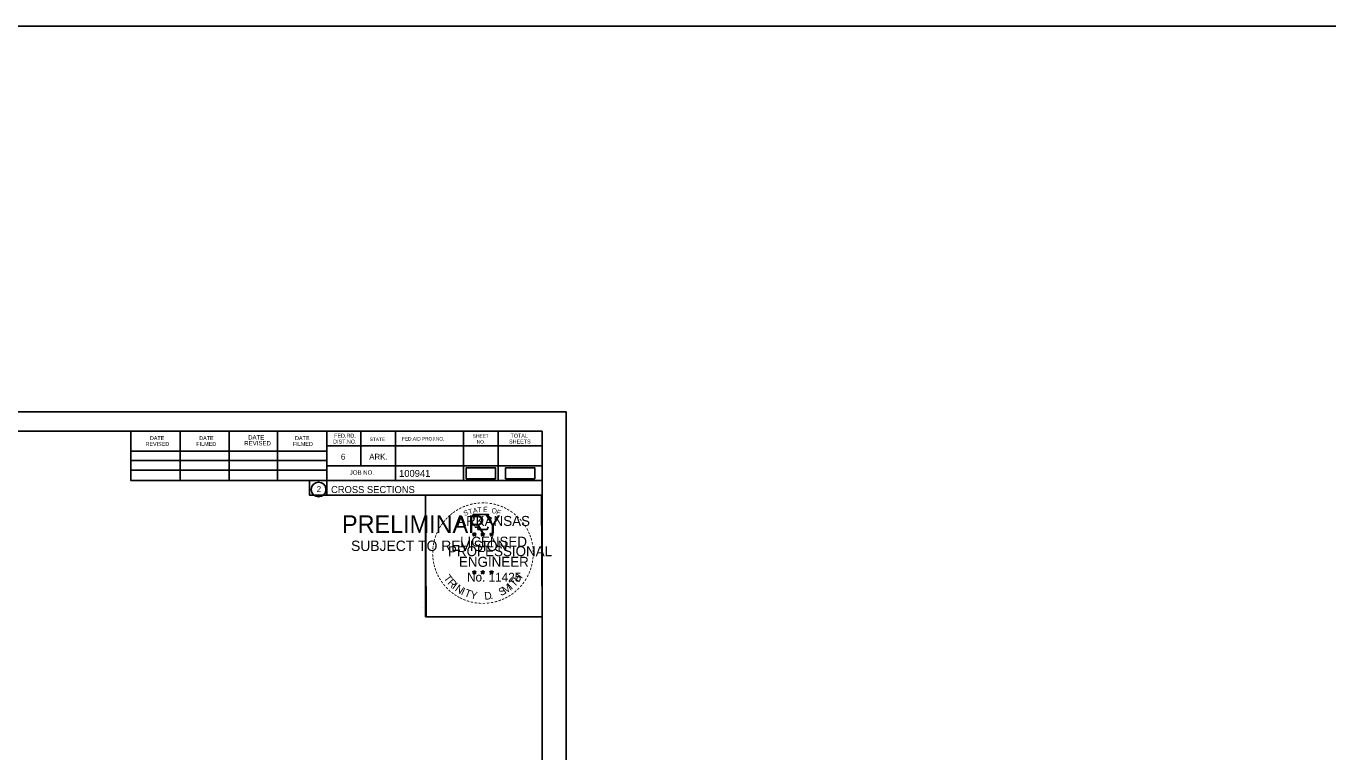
# Model space of a CAD drawing. Extents: x 1370538 to 1372872, y 376220 to 381127.
# Drawn here: x 1372096.9 to 1372357.3, y 380830.3 to 380975.6 of the extents above; entities that cross this region are included whole.
import ezdxf

# ---------------------------------------------------------------- set-up
doc = ezdxf.new("R2010")
doc.units = 0
for name, color, linetype in [('Default', 7, 'Continuous'), ('R_Border Notes', 7, 'Continuous'), ('R_No Plot', 7, 'Continuous'), ('T_Indications', 7, 'Continuous'), ('T_Notes', 7, 'Continuous')]:
    doc.layers.add(name, color=color, linetype=linetype)

msp = doc.modelspace()

# ---------------------------------------------------------------- linework, layer by layer
at = {"layer": 'Default'}
for points in [[(1372184.96, 380885), (1372190.79, 380885), (1372190.79, 380887.19), (1372184.96, 380887.19)], [(1372192.83, 380885), (1372198.66, 380885), (1372198.66, 380887.19), (1372192.83, 380887.19)]]:
    msp.add_lwpolyline(points, close=True, dxfattribs=at)
at = {"layer": 'R_Border Notes'}
for p, q in [((1371883.97, 380894.5), (1372200.15, 380894.5)), ((1372117.89, 380884.62), (1372117.89, 380894.5)), ((1372127.75, 380884.62), (1372127.75, 380894.3)), ((1372137.51, 380884.62), (1372137.51, 380894.3)), ((1372147.19, 380884.62), (1372147.19, 380894.3)), ((1372157.05, 380894.5), (1372157.05, 380881.7)), ((1372163.89, 380894.5), (1372163.89, 380887.56)), ((1372170.83, 380894.5), (1372170.83, 380884.62)), ((1372184.41, 380894.5), (1372184.41, 380884.62)), ((1372191.35, 380894.5), (1372191.35, 380884.62)), ((1372200.15, 380689.04), (1372200.15, 380894.5)), ((1372117.89, 380890.48), (1372157.05, 380890.48)), ((1372200.15, 380891.56), (1372157.05, 380891.56)), ((1372200.15, 380891.58), (1372200.15, 380891.58)), ((1372117.89, 380888.62), (1372157.05, 380888.62)), ((1372117.89, 380884.62), (1372117.89, 380886.68)), ((1372117.89, 380886.68), (1372157.05, 380886.68)), ((1372200.15, 380887.56), (1372157.05, 380887.56)), ((1372160.01, 380887.56), (1372200.15, 380887.56)), ((1372200.15, 380884.62), (1372117.89, 380884.62)), ((1372157.05, 380881.7), (1372200.15, 380881.7))]:
    msp.add_line(p, q, dxfattribs=at)
msp.add_circle((1372155.43, 380882.84), 1.47, dxfattribs=at)
at = {"layer": 'R_No Plot'}
for p, q in [((1370538.2, 380975.58), (1372871.58, 380975.58)), ((1371871.57, 380898.4), (1372204.9, 380898.4)), ((1372176.18, 380859.25), (1372176.18, 380859.25))]:
    msp.add_line(p, q, dxfattribs=at)
for points in [[(1371871.56, 380898.4), (1372204.9, 380898.4), (1372204.9, 380685.06), (1371871.56, 380685.06)], [(1372117.89, 380894.5), (1372117.89, 380884.62), (1372153.62, 380884.62), (1372153.62, 380881.7), (1372176.82, 380881.7), (1372176.82, 380857.37), (1372200.15, 380857.37), (1372200.15, 380689.04), (1371883.97, 380689.04), (1371883.97, 380894.5)], [(1372176.82, 380881.7), (1372200.03, 380881.7), (1372200.15, 380857.37), (1372176.94, 380857.37)]]:
    msp.add_lwpolyline(points, close=True, dxfattribs=at)
at = {"layer": 'T_Indications'}
for p, q in [((1372186.23, 380873.96), (1372186.58, 380873.85)), ((1372186.23, 380873.96), (1372186.48, 380873.91)), ((1372186.23, 380873.96), (1372186.47, 380873.84)), ((1372186.36, 380873.55), (1372186.58, 380873.85)), ((1372186.36, 380873.55), (1372186.49, 380873.8)), ((1372186.36, 380873.55), (1372186.58, 380873.77)), ((1372186.58, 380874.21), (1372186.54, 380873.96)), ((1372186.58, 380873.85), (1372186.58, 380874.21)), ((1372186.58, 380874.21), (1372186.63, 380873.96)), ((1372186.93, 380873.96), (1372186.58, 380873.85)), ((1372186.79, 380873.55), (1372186.58, 380873.85)), ((1372186.79, 380873.55), (1372186.58, 380873.77)), ((1372186.93, 380873.96), (1372186.64, 380873.91)), ((1372186.79, 380873.55), (1372186.66, 380873.84)), ((1372186.93, 380873.96), (1372186.72, 380873.86)), ((1372187.9, 380873.96), (1372188.25, 380873.85)), ((1372187.9, 380873.96), (1372188.15, 380873.91)), ((1372187.9, 380873.96), (1372188.14, 380873.84)), ((1372188.03, 380873.55), (1372188.25, 380873.85)), ((1372188.03, 380873.55), (1372188.16, 380873.8)), ((1372188.03, 380873.55), (1372188.25, 380873.77)), ((1372188.25, 380874.21), (1372188.21, 380873.96)), ((1372188.25, 380873.85), (1372188.25, 380874.21)), ((1372188.25, 380874.21), (1372188.3, 380873.96)), ((1372188.6, 380873.96), (1372188.25, 380873.85)), ((1372188.46, 380873.55), (1372188.25, 380873.85)), ((1372188.46, 380873.55), (1372188.25, 380873.77)), ((1372188.6, 380873.96), (1372188.31, 380873.91)), ((1372188.46, 380873.55), (1372188.33, 380873.84)), ((1372188.6, 380873.96), (1372188.39, 380873.86)), ((1372189.67, 380873.95), (1372190.01, 380873.84)), ((1372189.67, 380873.95), (1372189.92, 380873.9)), ((1372189.67, 380873.95), (1372189.9, 380873.83)), ((1372189.8, 380873.54), (1372190.01, 380873.84)), ((1372189.8, 380873.54), (1372189.92, 380873.78)), ((1372189.8, 380873.54), (1372190.01, 380873.76)), ((1372190.01, 380874.2), (1372189.97, 380873.95)), ((1372190.01, 380873.84), (1372190.01, 380874.2)), ((1372190.01, 380874.2), (1372190.06, 380873.95)), ((1372190.36, 380873.95), (1372190.01, 380873.84)), ((1372190.23, 380873.54), (1372190.01, 380873.84)), ((1372190.23, 380873.54), (1372190.01, 380873.75)), ((1372190.36, 380873.95), (1372190.08, 380873.9)), ((1372190.23, 380873.54), (1372190.09, 380873.83)), ((1372190.36, 380873.95), (1372190.16, 380873.85)), ((1372186.23, 380866.39), (1372186.58, 380866.28)), ((1372186.23, 380866.39), (1372186.48, 380866.34)), ((1372186.23, 380866.39), (1372186.46, 380866.26)), ((1372186.36, 380865.98), (1372186.58, 380866.28)), ((1372186.36, 380865.98), (1372186.49, 380866.22)), ((1372186.36, 380865.98), (1372186.57, 380866.2)), ((1372186.58, 380866.64), (1372186.54, 380866.39)), ((1372186.79, 380865.98), (1372186.57, 380866.19)), ((1372186.58, 380866.28), (1372186.58, 380866.64)), ((1372186.58, 380866.64), (1372186.63, 380866.39)), ((1372186.92, 380866.39), (1372186.58, 380866.28)), ((1372186.79, 380865.98), (1372186.58, 380866.28)), ((1372186.92, 380866.39), (1372186.64, 380866.34)), ((1372186.79, 380865.98), (1372186.65, 380866.27)), ((1372186.92, 380866.39), (1372186.72, 380866.28)), ((1372187.9, 380866.39), (1372188.25, 380866.28)), ((1372187.9, 380866.39), (1372188.15, 380866.34)), ((1372187.9, 380866.39), (1372188.13, 380866.26)), ((1372188.03, 380865.98), (1372188.25, 380866.28)), ((1372188.03, 380865.98), (1372188.16, 380866.22)), ((1372188.03, 380865.98), (1372188.24, 380866.2)), ((1372188.25, 380866.64), (1372188.2, 380866.39)), ((1372188.46, 380865.98), (1372188.24, 380866.19)), ((1372188.25, 380866.28), (1372188.25, 380866.64)), ((1372188.25, 380866.64), (1372188.29, 380866.39)), ((1372188.59, 380866.39), (1372188.25, 380866.28)), ((1372188.46, 380865.98), (1372188.25, 380866.28)), ((1372188.59, 380866.39), (1372188.31, 380866.34)), ((1372188.46, 380865.98), (1372188.32, 380866.27)), ((1372188.59, 380866.39), (1372188.39, 380866.28)), ((1372189.66, 380866.38), (1372190.01, 380866.27)), ((1372189.66, 380866.38), (1372189.92, 380866.33)), ((1372189.66, 380866.38), (1372189.9, 380866.25)), ((1372189.8, 380865.97), (1372190.01, 380866.27)), ((1372189.8, 380865.97), (1372189.92, 380866.21)), ((1372189.8, 380865.97), (1372190.01, 380866.19)), ((1372190.01, 380866.63), (1372189.97, 380866.38)), ((1372190.01, 380866.27), (1372190.01, 380866.63)), ((1372190.01, 380866.63), (1372190.06, 380866.38)), ((1372190.36, 380866.38), (1372190.01, 380866.27)), ((1372190.23, 380865.97), (1372190.01, 380866.27)), ((1372190.23, 380865.97), (1372190.01, 380866.18)), ((1372190.36, 380866.38), (1372190.07, 380866.33)), ((1372190.23, 380865.97), (1372190.09, 380866.26)), ((1372190.36, 380866.38), (1372190.16, 380866.27))]:
    msp.add_line(p, q, dxfattribs=at)
for points in [[(1372186.27, 380877.84), (1372186.54, 380877.01)], [(1372189.78, 380876.92), (1372189.93, 380877.2), (1372189.24, 380877.18), (1372189.39, 380877.84), (1372186.27, 380877.84)], [(1372186.76, 380875.41), (1372186.76, 380875.33), (1372187.33, 380875.31), (1372187.27, 380874.84), (1372189.14, 380874.84), (1372189.34, 380875.37)], [(1372186.58, 380874.21), (1372186.79, 380873.55), (1372186.23, 380873.96), (1372186.93, 380873.96), (1372186.36, 380873.55), (1372186.58, 380874.21)], [(1372188.25, 380874.21), (1372188.46, 380873.55), (1372187.9, 380873.96), (1372188.6, 380873.96), (1372188.03, 380873.55), (1372188.25, 380874.21)], [(1372190.01, 380874.2), (1372190.23, 380873.54), (1372189.67, 380873.95), (1372190.36, 380873.95), (1372189.8, 380873.54), (1372190.01, 380874.2)], [(1372186.58, 380866.64), (1372186.79, 380865.98), (1372186.23, 380866.39), (1372186.92, 380866.39), (1372186.36, 380865.98), (1372186.58, 380866.64)], [(1372188.25, 380866.64), (1372188.46, 380865.98), (1372187.9, 380866.39), (1372188.59, 380866.39), (1372188.03, 380865.98), (1372188.25, 380866.64)], [(1372190.01, 380866.63), (1372190.23, 380865.97), (1372189.66, 380866.38), (1372190.36, 380866.38), (1372189.8, 380865.97), (1372190.01, 380866.63)]]:
    msp.add_lwpolyline(points, dxfattribs=at)
for centre, radius in [((1372186.58, 380873.85), 0.172), ((1372186.58, 380873.85), 0.145), ((1372186.58, 380873.85), 0.116), ((1372186.58, 380873.85), 0.0991), ((1372186.58, 380873.85), 0.0747), ((1372186.58, 380873.85), 0.0495), ((1372186.58, 380873.85), 0.0296), ((1372188.25, 380873.85), 0.172), ((1372188.25, 380873.85), 0.145), ((1372188.25, 380873.85), 0.116), ((1372188.25, 380873.85), 0.0991), ((1372188.25, 380873.85), 0.0747), ((1372188.25, 380873.85), 0.0495), ((1372188.25, 380873.85), 0.0296), ((1372190.01, 380873.84), 0.172), ((1372190.01, 380873.84), 0.145), ((1372190.01, 380873.84), 0.116), ((1372190.01, 380873.84), 0.0991), ((1372190.01, 380873.84), 0.0747), ((1372190.01, 380873.84), 0.0495), ((1372190.01, 380873.84), 0.0296), ((1372186.58, 380866.27), 0.172), ((1372186.58, 380866.27), 0.145), ((1372186.58, 380866.27), 0.116), ((1372186.58, 380866.27), 0.0991), ((1372186.58, 380866.27), 0.0747), ((1372186.58, 380866.27), 0.0495), ((1372186.58, 380866.27), 0.0296), ((1372188.24, 380866.27), 0.172), ((1372188.24, 380866.27), 0.145), ((1372188.24, 380866.27), 0.116), ((1372188.24, 380866.27), 0.0991), ((1372188.24, 380866.27), 0.0747), ((1372188.24, 380866.27), 0.0495), ((1372188.24, 380866.27), 0.0296), ((1372190.01, 380866.26), 0.172), ((1372190.01, 380866.26), 0.145), ((1372190.01, 380866.26), 0.116), ((1372190.01, 380866.26), 0.0991), ((1372190.01, 380866.26), 0.0747), ((1372190.01, 380866.26), 0.0495), ((1372190.01, 380866.26), 0.0296)]:
    msp.add_circle(centre, radius, dxfattribs=at)

# ---------------------------------------------------------------- texts
at = {"layer": 'R_Border Notes'}
for s, height, p in [('DATE', 0.782, (1372121.69, 380892.74)), ('DATE', 0.782, (1372131.55, 380892.74)), ('DATE', 0.879, (1372141.33, 380892.84)), ('DATE', 0.782, (1372150.71, 380892.74)), ('FED.RD.', 0.782, (1372158.53, 380893.22)), ('STATE', 0.684, (1372165.65, 380892.54)), ('FED.AID PROJ.NO.', 0.684, (1372172.11, 380892.64)), ('SHEET', 0.684, (1372186.27, 380893.22)), ('TOTAL', 0.782, (1372193.79, 380893.22)), ('REVISED', 0.782, (1372120.81, 380891.56)), ('FILMED', 0.782, (1372130.97, 380891.56)), ('REVISED', 0.879, (1372140.55, 380891.66)), ('FILMED', 0.782, (1372150.31, 380891.56)), ('DIST.NO.', 0.782, (1372158.33, 380892.04)), ('NO.', 0.684, (1372187.05, 380892.04)), ('SHEETS', 0.782, (1372193.51, 380892.04)), ('6', 1.17, (1372159.89, 380888.82)), ('ARK.', 1.172, (1372165.55, 380888.82)), ('JOB NO.', 0.879, (1372161.65, 380885.8)), ('100941', 1.4, (1372171.52, 380885.36)), ('2', 1.17, (1372155.05, 380882.35)), ('CROSS SECTIONS', 1.4, (1372157.91, 380882.13))]:
    msp.add_text(s, height=height, rotation=360, dxfattribs=at).set_placement(p)
at = {"layer": 'T_Indications'}
for s, height, rotation, p in [('-', 1.6, 13.6301, (1372185.77, 380879.21)), ('-', 1.6, 10.2193, (1372186.45, 380879.37)), ('-', 1.6, 5.8968, (1372187.18, 380879.48)), ('-', 1.6, 0.1862, (1372187.95, 380879.55)), ('-', 1.6, 357.743, (1372188.67, 380879.54)), ('-', 1.6, 352.1617, (1372189.42, 380879.48)), ('-', 1.6, 347.2049, (1372190.14, 380879.37)), ('-', 1.6, 342.3362, (1372190.77, 380879.21)), ('-', 1.6, 48.423, (1372181.22, 380876.34)), ('-', 1.6, 42.9622, (1372181.67, 380876.82)), ('-', 1.6, 38.9507, (1372182.1, 380877.24)), ('-', 1.6, 36.2317, (1372182.58, 380877.61)), ('-', 1.6, 34.0636, (1372183.16, 380878.01)), ('ARKANSAS', 2, 360, (1372183.13, 380875.55)), ('-', 1.6, 28.7918, (1372183.75, 380878.38)), ('-', 1.6, 24.3072, (1372184.39, 380878.7)), ('S', 1, 21.594, (1372184.63, 380877.52)), ('-', 1.6, 19.1761, (1372185.02, 380878.96)), ('T', 1, 16.4036, (1372185.54, 380877.85)), ('A', 1, 11.2132, (1372186.37, 380878.1)), ('T', 1, 6.0228, (1372187.22, 380878.26)), ('E', 1, 0.8323, (1372188.32, 380878.37)), ('O', 1, 350.4515, (1372189.93, 380878.16)), ('F', 1, 340.0707, (1372190.88, 380877.94)), ('-', 1.6, 337.8551, (1372191.51, 380878.99)), ('-', 1.6, 334.1211, (1372192.14, 380878.72)), ('-', 1.6, 329.6409, (1372192.72, 380878.43)), ('-', 1.6, 325.8627, (1372193.36, 380878.07)), ('-', 1.6, 320.5297, (1372193.97, 380877.65)), ('-', 1.6, 315.5786, (1372194.57, 380877.16)), ('-', 1.6, 62.8713, (1372179.77, 380874.15)), ('-', 1.6, 58.0706, (1372180.08, 380874.76)), ('-', 1.6, 54.2325, (1372180.41, 380875.29)), ('-', 1.6, 50.6142, (1372180.82, 380875.85)), ('-', 1.6, 309.8797, (1372195.14, 380876.61)), ('-', 1.6, 306.6522, (1372195.66, 380876.01)), ('-', 1.4, 303.6753, (1372196.15, 380875.44)), ('-', 1.6, 299.6684, (1372196.47, 380874.83)), ('-', 1.6, 81.2013, (1372178.96, 380871.48)), ('-', 1.6, 75.461, (1372179.09, 380872.19)), ('-', 1.6, 72.3945, (1372179.29, 380872.91)), ('-', 1.6, 67.7743, (1372179.51, 380873.54)), ('LICENSED', 2, 360, (1372183.72, 380871.4)), ('DWB', 0.01, 360, (1372186.57, 380873.84)), ('DWB', 0.01, 360, (1372188.24, 380873.84)), ('DWB', 0.01, 360, (1372190, 380873.83)), ('-', 1.6, 294.6628, (1372196.79, 380874.22)), ('-', 1.6, 290.5728, (1372197.05, 380873.64)), ('-', 1.6, 285.1233, (1372197.28, 380873.06)), ('-', 1.6, 280.5493, (1372197.48, 380872.32)), ('-', 1.6, 94.1959, (1372178.89, 380869.36)), ('-', 1.6, 89.0622, (1372178.86, 380870.09)), ('-', 1.6, 85.1863, (1372178.88, 380870.79)), ('PROFESSIONAL', 2, 360, (1372181.3, 380869.5)), ('-', 1.6, 276.5962, (1372197.64, 380871.55)), ('-', 1.6, 274.3301, (1372197.7, 380870.83)), ('-', 1.6, 269.9407, (1372197.74, 380870.2)), ('-', 1.6, 98.9479, (1372178.97, 380868.69)), ('-', 1.6, 101.7149, (1372179.1, 380867.96)), ('-', 1.6, 105.4578, (1372179.26, 380867.37)), ('-', 1.6, 109.0874, (1372179.48, 380866.74)), ('ENGINEER', 2, 360, (1372183.49, 380867.37)), ('-', 1.6, 252.8681, (1372197.36, 380867.48)), ('-', 1.6, 255.7626, (1372197.54, 380868.2)), ('-', 1.6, 260.9953, (1372197.65, 380868.88)), ('-', 1.6, 263.5172, (1372197.72, 380869.53)), ('-', 1.6, 114.0643, (1372179.73, 380866.14)), ('-', 1.6, 115.7289, (1372180.04, 380865.52)), ('-', 1.6, 120.4471, (1372180.39, 380864.94)), ('-', 1.6, 125.8934, (1372180.8, 380864.37)), ('T', 1.54, 306.0406, (1372180.34, 380865.11)), ('R', 1.54, 314.005, (1372181.1, 380864.07)), ('No. 11425', 1.757, 360, (1372185.11, 380864.42)), ('DWB', 0.01, 360, (1372186.56, 380866.27)), ('DWB', 0.01, 360, (1372188.23, 380866.27)), ('DWB', 0.01, 360, (1372190, 380866.26)), ('T', 1.54, 46.6444, (1372194.57, 380863.21)), ('H', 1.54, 54.6088, (1372195.46, 380864.15)), ('-', 1.6, 233.8452, (1372196.08, 380864.77)), ('-', 1.6, 239.0712, (1372196.48, 380865.43)), ('-', 1.6, 244.6197, (1372196.87, 380866.18)), ('-', 1.6, 247.8887, (1372197.13, 380866.81)), ('-', 1.6, 130.7181, (1372181.26, 380863.82)), ('-', 1.6, 134.2238, (1372181.78, 380863.28)), ('-', 1.6, 138.9338, (1372182.3, 380862.81)), ('-', 1.6, 144.6463, (1372182.86, 380862.41)), ('I', 1.54, 321.9694, (1372182, 380863.13)), ('-', 1.6, 148.0898, (1372183.42, 380862.04)), ('N', 1.54, 326.5002, (1372182.57, 380862.66)), ('I', 1.54, 335.3603, (1372183.77, 380861.88)), ('T', 1.54, 339.8912, (1372184.44, 380861.55)), ('Y', 1.54, 347.8556, (1372185.65, 380861.1)), ('D', 1.54, 6.3969, (1372188.64, 380860.75)), ('S', 1.54, 26.9312, (1372191.88, 380861.48)), ('M', 1.54, 32.6563, (1372192.72, 380861.88)), ('I', 1.54, 42.1136, (1372194, 380862.73)), ('-', 1.6, 212.2491, (1372193.56, 380862.28)), ('-', 1.6, 215.7363, (1372194.1, 380862.66)), ('-', 1.6, 221.0851, (1372194.64, 380863.14)), ('-', 1.6, 225.7653, (1372195.17, 380863.64)), ('-', 1.6, 231.2538, (1372195.65, 380864.21)), ('-', 1.6, 151.5704, (1372184, 380861.71)), ('-', 1.6, 154.6002, (1372184.52, 380861.46)), ('-', 1.6, 158.5612, (1372185.14, 380861.21)), ('-', 1.6, 162.7983, (1372185.83, 380861)), ('-', 1.6, 167.5555, (1372186.55, 380860.83)), ('-', 1.6, 173.1155, (1372187.32, 380860.72)), ('-', 1.6, 176.5183, (1372188.07, 380860.67)), ('-', 1.6, 181.5918, (1372188.81, 380860.69)), ('-', 1.6, 185.8167, (1372189.62, 380860.77)), ('-', 1.6, 191.2858, (1372190.35, 380860.9)), ('.', 1.54, 13.7642, (1372189.83, 380860.87)), ('-', 1.6, 195.4743, (1372191.08, 380861.1)), ('-', 1.6, 200.7184, (1372191.76, 380861.34)), ('-', 1.6, 204.2516, (1372192.38, 380861.61)), ('-', 1.6, 207.3568, (1372193, 380861.93))]:
    msp.add_text(s, height=height, rotation=rotation, dxfattribs=at).set_placement(p)
at = {"layer": 'T_Notes'}
for s, height, p in [('PRELIMINARY', 3.5, (1372160.1, 380874.17)), ('DWB', 0.01, (1372160.84, 380876.02)), ('SUBJECT TO REVISION', 2.0751, (1372161.91, 380870.54))]:
    msp.add_text(s, height=height, rotation=360, dxfattribs=at).set_placement(p)

doc.saveas('drawing.dxf')
